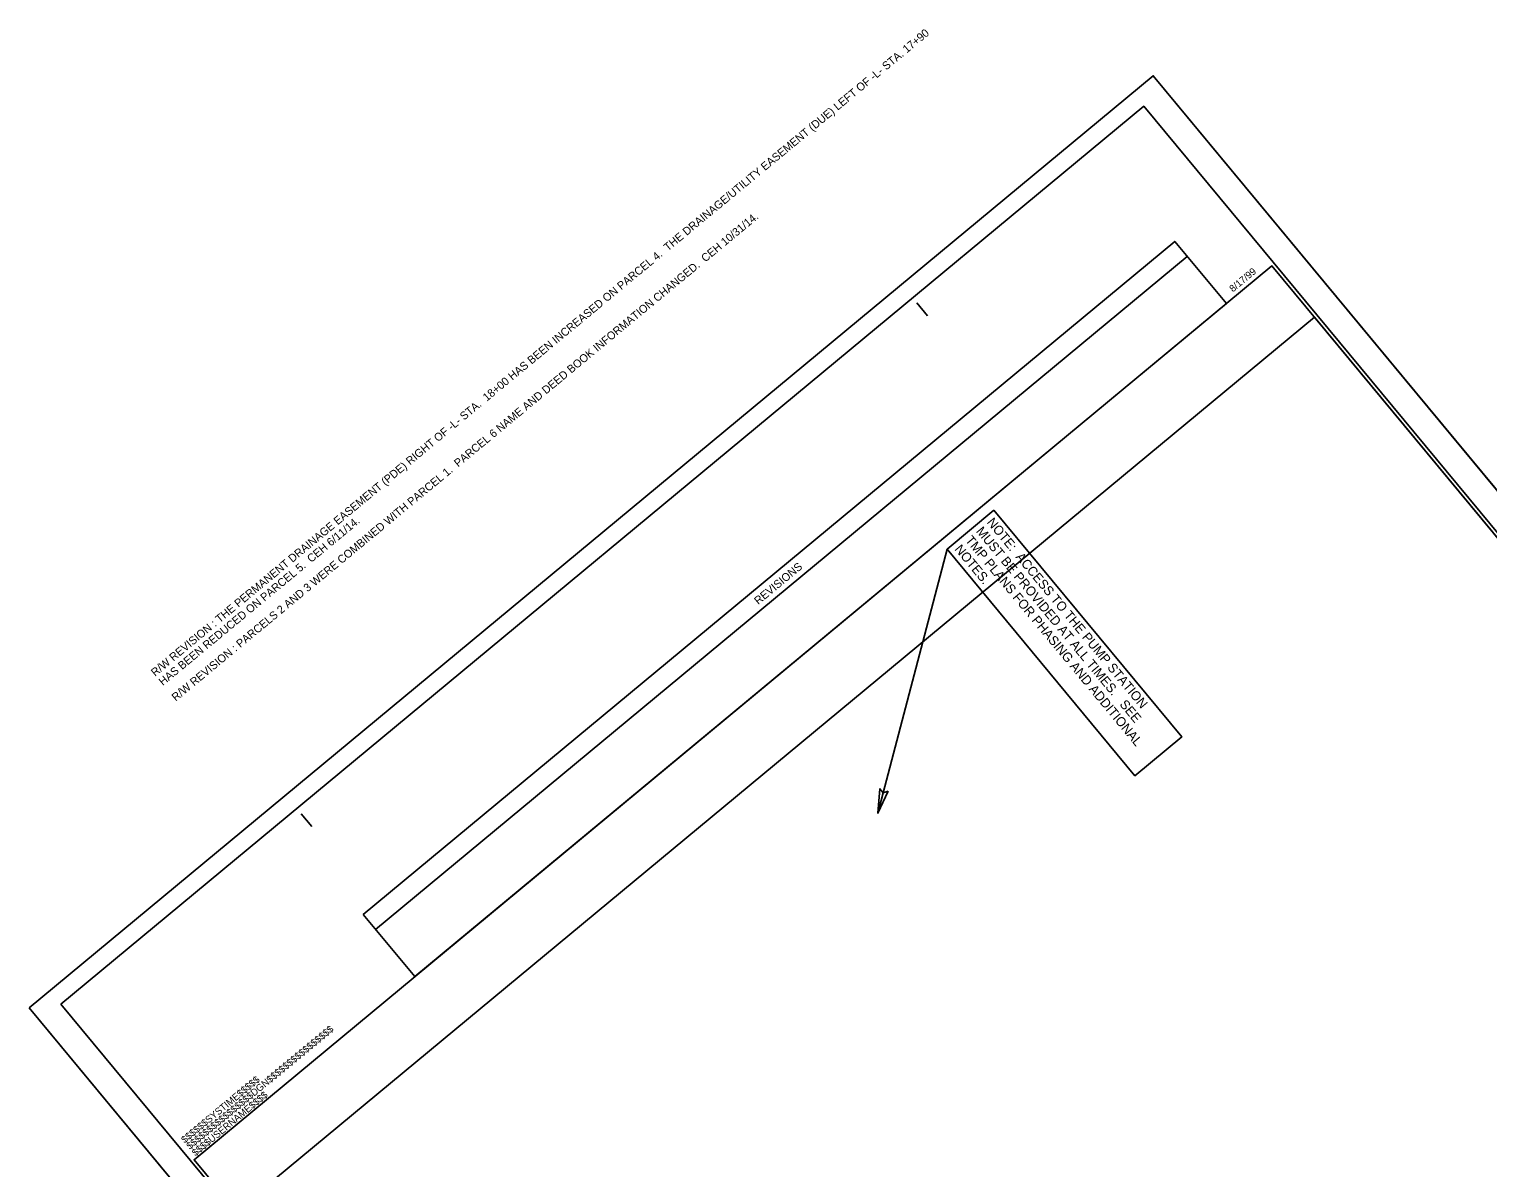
# Model space of a CAD drawing. Extents: x 2057815 to 2059783, y 687683 to 689713.
# Drawn here: x 2057815 to 2058909, y 688859 to 689713 of the extents above; entities that cross this region are included whole.
import ezdxf

# ---------------------------------------------------------------- set-up
doc = ezdxf.new("R2010")
doc.units = 0
for name, color, linetype in [('Prop Dimension Text', 7, 'Continuous'), ('Prop Terminator CELL', 7, 'Continuous'), ('Sheet Block Revision CELL', 7, 'Continuous'), ('Sheet Clip Boundary CELL', 7, 'Continuous'), ('Sheet Cutting Line CELL', 7, 'Continuous'), ('Sheet Layout Plan Border', 7, 'Continuous'), ('Sheet Plan CELL', 7, 'Continuous'), ('Sheet Plan Layout CELL', 7, 'Continuous'), ('Sheet Plot Border Inside CELL', 7, 'Continuous'), ('Sheet Plot Border Outside CELL', 7, 'Continuous')]:
    doc.layers.add(name, color=color, linetype=linetype)

msp = doc.modelspace()

# ---------------------------------------------------------------- linework, layer by layer
at = {"layer": 'Prop Dimension Text'}
msp.add_line((2058503.4, 689323), (2058451.5, 689125), dxfattribs=at)
msp.add_lwpolyline([(2058538.5, 689352.2), (2058679.4, 689182.3), (2058644.2, 689153.2), (2058503.4, 689323)], close=True, dxfattribs=at)
at = {"layer": 'Prop Terminator CELL'}
msp.add_lwpolyline([(2058459.1, 689141.7), (2058451.5, 689125), (2058453, 689143.4), (2058455.5, 689140.3)], close=True, dxfattribs=at)
at = {"layer": 'Sheet Block Revision CELL'}
msp.add_line((2058074.8, 689037.9), (2058683.4, 689542.6), dxfattribs=at)
msp.add_lwpolyline([(2058065.5, 689049.1), (2058674.1, 689553.8), (2058712.8, 689507.2), (2058104.2, 689002.5)], close=True, dxfattribs=at)
at = {"layer": 'Sheet Clip Boundary CELL'}
msp.add_lwpolyline([(2057970.6, 688826.8), (2058864.2, 687749.1), (2059509.7, 688284.3), (2059388.9, 688430), (2059551.7, 688565), (2058778.8, 689497)], close=True, dxfattribs=at)
at = {"layer": 'Sheet Cutting Line CELL'}
for p, q in [((2058658, 689678), (2057815.1, 688979)), ((2059732.6, 688382.1), (2058658, 689678)), ((2057815.1, 688979), (2058889.7, 687683.1))]:
    msp.add_line(p, q, dxfattribs=at)
at = {"layer": 'Sheet Layout Plan Border'}
msp.add_lwpolyline([(2057970.6, 688826.8), (2058864.2, 687749.1), (2059509.7, 688284.3), (2059388.9, 688430), (2059551.7, 688565), (2058778.8, 689497)], close=True, dxfattribs=at)
at = {"layer": 'Sheet Plan CELL'}
for p, q in [((2058746.9, 689535.5), (2058746.9, 689535.5)), ((2058480.8, 689507.8), (2058488.8, 689498.1)), ((2058019, 689124.7), (2058027, 689115.1)), ((2057938.7, 688865.2), (2057938.7, 688865.2))]:
    msp.add_line(p, q, dxfattribs=at)
for points in [[(2059704.4, 688380.8), (2058746.9, 689535.5), (2057938.7, 688865.2), (2058896.2, 687710.6)], [(2057938.7, 688865.2), (2058746.9, 689535.5), (2059576.7, 688534.8), (2059461.2, 688439), (2059588.9, 688285), (2058896.2, 687710.6)]]:
    msp.add_lwpolyline(points, close=True, dxfattribs=at)
at = {"layer": 'Sheet Plan Layout CELL'}
msp.add_lwpolyline([(2058746.9, 689535.5), (2057938.7, 688865.2), (2058896.2, 687710.6), (2059541.6, 688245.8), (2059388.9, 688430), (2059551.7, 688565)], close=True, dxfattribs=at)
at = {"layer": 'Sheet Plot Border Inside CELL'}
msp.add_lwpolyline([(2057838.8, 688981.8), (2058902.2, 687699.4), (2059714.3, 688372.8), (2058650.9, 689655.2)], close=True, dxfattribs=at)
at = {"layer": 'Sheet Plot Border Outside CELL'}
msp.add_lwpolyline([(2057815.1, 688979), (2058889.7, 687683.1), (2059732.6, 688382.1), (2058658, 689678)], close=True, dxfattribs=at)

# ---------------------------------------------------------------- texts
at = {"layer": 'Prop Dimension Text'}
for s, p in [('NOTE:  ACCESS TO THE PUMP STATION', (2058532.8, 689343)), ('MUST BE PROVIDED AT ALL TIMES.   SEE', (2058524.7, 689336.3)), ('NOTES.', (2058508.6, 689322.9)), ('TMP PLANS FOR PHASING AND ADDITIONAL ', (2058516.6, 689329.6))]:
    msp.add_text(s, height=7, rotation=309.6672, dxfattribs=at).set_placement(p)
at = {"layer": 'Sheet Block Revision CELL'}
for s, p in [('R/W REVISION : THE PERMANENT DRAINAGE EASEMENT (PDE) RIGHT OF -L- STA.  18+00 HAS BEEN INCREASED ON PARCEL 4.  THE DRAINAGE/UTILITY EASEMENT (DUE) LEFT OF -L- STA. 17+90', (2057909.5, 689227.3)), ('R/W REVISION : PARCELS 2 AND 3 WERE COMBINED WITH PARCEL 1.  PARCEL 6 NAME AND DEED BOOK INFORMATION CHANGED.  CEH 10/31/14.', (2057925, 689208.7)), ('HAS BEEN REDUCED ON PARCEL 5.  CEH 6/11/14.', (2057915.3, 689220.4)), ('REVISIONS', (2058361.8, 689281.1))]:
    msp.add_text(s, height=6, rotation=39.6672, dxfattribs=at).set_placement(p)
at = {"layer": 'Sheet Plan CELL'}
for s, p in [('8/17/99', (2058717.7, 689515.5)), ('$$$$$$$$$$$$$$$$DGN$$$$$$$$$$$$$$$$', (2057935.6, 688872.6)), ('$$$$$$SYSTIME$$$$$', (2057931.7, 688877.3)), ('$$$$USERNAME$$$$', (2057939.8, 688867.6))]:
    msp.add_text(s, height=5.25, rotation=39.6672, dxfattribs=at).set_placement(p)

doc.saveas('drawing.dxf')
